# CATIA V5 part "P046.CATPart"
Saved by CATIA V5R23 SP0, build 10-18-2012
Part number: 05-LICP-T02-E-S02-P046
Definition: Axe Du Coulisseau
Bounding box of the stored display mesh (mm): x -27 to 27, y -8 to 8, z -7.956 to 7.956
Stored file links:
  C:\wamp\www\COURS\CONCEPTION GMP1\TITRE 02-SEMESTRE 2\03-TP7-PRESSE MECANIQUE\eleve\P046.CATPart
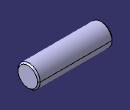
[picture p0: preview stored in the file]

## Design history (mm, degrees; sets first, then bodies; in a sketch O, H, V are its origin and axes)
Body1 (main body)
  Sketch1 on yz-plane, origin (0, 0, 0), H (0, 1, 0), V (0, 0, 1)
    circle A1 centre (0, 0) radius 8
    radius A1 = 8
  Pad1: profile Sketch1, direction (1, 0, 0), length 27, mirrored extent
  Chamfer1: length 1, angle 45, on face of Pad1; edge [face of Pad1 | face of Pad1]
